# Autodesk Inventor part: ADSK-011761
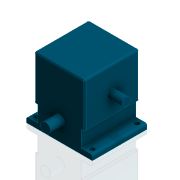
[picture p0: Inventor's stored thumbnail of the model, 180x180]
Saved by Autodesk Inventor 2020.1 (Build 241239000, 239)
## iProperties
Created: 1999-12
Part Number: ADSK-011761
Document SubType Name: Modeling
Designer: glanglot
Material: Acier doux
Density: 7.86 g/cm^3
Appearance: Bearing Blue
Mass: 10200.3 g
Surface Area: 842.915 cm^2
Volume: 1297.74 cm^3
Control State: 0
Checked Out: False
Last Check In By: glanglot
Last Check In Date: 1999-12-14
Master: False
Shininess: 60.0
Length Units: 11269
Angle Units: 11279
Time Units: 11290
Mass Units: 11283
Length Display Precision: 3
Angle Display Precision: 2
Compacted: True
Dimensions: 140x127x158 mm
Mass: 10,2 kg
DocNumber: ADSK-011761.ipt
Folder: 01 - Themengebiete\Simplification\01 - Packaging machine\
VDS_Category: 3D Komponenten
Density: 0.0
Volumn: 0.0
Area: 0.0
PropertySet Name: Model Information
Author: glanglot
Revision Number: -
Title: gearbox
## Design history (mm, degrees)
node "Solide1"
  node "Extrusion1" dims "d2" = 105, "d3" = 0
  node "Extrusion2" dims "d14" = 104.775, "d15" = 0
  node "Extrusion3" dims "d18" = 158, "d19" = 0
  node "Extrusion4" dims "d24" = 76, "d25" = 0
  node "Hole1" dims "d34" = 9, "d35" = 9.525, "d36" = 6.35, "d37" = 60 deg, "d38" = 10.414, "d39" = 118 deg, "d50" = 6
  node "Fillet1" dims "d40" = 3
sketch "Sketch1"
  geometry: L1 (-63.5, -66)-(63.5, -66); L2 (63.5, -66)-(63.5, 66); L3 (63.5, 66)-(-63.5, 66); L4 (-63.5, 66)-(-63.5, -66); 3 further points
  constraints: 8 end point, 2 midpoint, 2 parallel, 1 horizontal, 1 horizontal alignment, 1 perpendicular, 1 vertical alignment
  dimensions: "d0" = 132 distance of L3.end L1.start; "d1" = 127 distance of L1.start L1.end
sketch "Sketch2"
  geometry: L1 (-63.5, -66)-(-63.5, 66) reference; L2 (63.5, -66)-(-63.5, -66) reference; L3 (63.5, 66)-(63.5, -66) reference; L4 (-63.5, 66)-(63.5, 66) reference; L5 (-63.5, -66)-(-63.5, -56); L6 (-63.5, -56)-(-42, -56); L7 (-42, -56)-(-42, -24.25); L8 (-42, -24.25)-(-48.5, -24.25); L9 (-48.5, -24.25)-(-48.5, 61); L10 (48.5, 61)-(48.5, -24.25); L11 (48.5, -24.25)-(42, -24.25); L12 (42, -24.25)-(42, -56); L13 (42, -56)-(63.5, -56); L14 (0, 66)-(0, -66); L15 (-48.5, 61)-(48.5, 61); 1 further point
  constraints: 22 end point, 3 collinear, 3 midpoint, 3 parallel, 3 perpendicular, 3 point on line, 1 horizontal, 1 vertical
  dimensions: "d9" = 10 distance between parallel lines of L2 L13; "d10" = 31.75 distance of L6.end L7.end; "d45" = 84 distance between parallel lines of L12 L7; "d46" = 127 distance between parallel lines of L15 L2; "d47" = 97 distance of L9.end L10.start
workplane "Work Plane1"
sketch "Sketch4"
  geometry: L1 (63.5, -66)-(-63.5, -66) reference; L2 (-42, -24.25)-(-42, -56) reference; C1 r 9.5 at (0, -29.5); 1 further point
  constraints: 1 centre point, 1 midpoint, 1 vertical alignment
  dimensions: "d20" = 19 diameter of C1; "d43" = 36.5 distance from line of C1.centre L1
workplane "Work Plane2"
sketch "Sketch6"
  geometry: L1 (0, -41.75)-(-105, -41.75) reference; L2 (-105, -31.75)-(-105, -41.75) reference; L3 (-105, 85.25)-(0, 85.25) reference; C1 r 8 at (-52.5, 37.25); 1 further point
  constraints: 1 centre point, 1 midpoint, 1 vertical alignment
  dimensions: "d22" = 16 diameter of C1; "d41" = 79 distance from line of C1.centre L1
sketch "Sketch7"
  geometry: L1 (127, 105)-(0, 105) reference; L2 (0, 0)-(0, 105) reference; L3 (9.5, 95.5)-(117.5, 95.5); L4 (117.5, 95.5)-(117.5, 9.5); L5 (117.5, 9.5)-(9.5, 9.5); L6 (9.5, 9.5)-(9.5, 95.5); 6 further points
  constraints: 8 end point, 4 midpoint, 2 coincident, 2 parallel, 1 horizontal, 1 horizontal alignment, 1 perpendicular, 1 vertical alignment
  dimensions: "d48" = 86 distance of L5.end L3.start; "d49" = 108 distance of L3.start L3.end
node "Corps solides"
node "Corps surfaciques"
other parameters: "d17" = -52.3875, "d21" = 28
